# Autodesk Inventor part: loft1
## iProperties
Shininess: 64.0
Length Units: 11269
Angle Units: 11279
Time Units: 11290
Mass Units: 11283
Length Display Precision: 3
Angle Display Precision: 2
Compacted: True
Part Number: loft1
Document SubType Name: Modeling
Created: 2002-12
Designer: deepak
Density: 1 g/cm^3
Density: 0.0
Volumn: 0.0
Area: 0.0
PropertySet Name: Model Information
Control State: 0
Master: False
Checked Out: False
Author: deepak
